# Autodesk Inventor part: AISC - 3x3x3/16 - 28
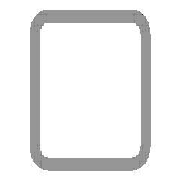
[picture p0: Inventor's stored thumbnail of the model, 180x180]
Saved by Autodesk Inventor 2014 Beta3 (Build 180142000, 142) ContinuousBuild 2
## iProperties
IsCustomPart: 1
_CCFamilyMember: 9
_CCFamilyDisplayName: ANSI AISC (Square) - Tube
_FrameMemberDoc: Frame Member File
_Version: 15.0.0
_GetPNFromCC: 1
Created: 2011-01
Part Number: AISC - 3x3x3/16 - 28
Material: Steel, Mild
Description: Tube
Document SubType Name: Modeling
Standard: ANSI
Designer: Beta-8540w
Standards Organization: ANSI
Language: en-US
Size Designation: 3x3x3/16
Categories: <MemberInstance><Categories><Category DisplayName="Structural Shapes" InternalName="089c4875-fa83-4c05-b084-43b9cc11f5ed" Mnemonic="GRDR"><CategoryParameter Dis
Stock Number: 3x3x3/16
Density: 7.86 g/cm^3
Appearance: Steel
G_L: 28.000 in
G_W: 3.000 in
G_H: 3.000 in
Author: Beta-8540w
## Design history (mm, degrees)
node "Start plane"
node "End plane"
sketch "Sketch"
  geometry: L1 (-38.1, -28.575)-(-38.1, 28.575); L2 (-28.575, 38.1)-(28.575, 38.1); L3 (38.1, 28.575)-(38.1, -28.575); L4 (28.575, -38.1)-(-28.575, -38.1); L5 (-28.575, 33.337)-(28.575, 33.338); L6 (33.338, 28.575)-(33.338, -28.575); L7 (28.575, -33.337)-(-28.575, -33.338); L8 (-33.338, -28.575)-(-33.338, 28.575); L9 (0, 56.102)-(0, -56.102) reference; L10 (-56.102, 0)-(56.102, 0) reference; A1 r 9.525 centre (-28.575, -28.575) between (-38.1, -28.575) and (-28.575, -38.1); A2 r 9.525 centre (-28.575, 28.575) between (-28.575, 38.1) and (-38.1, 28.575); A3 r 9.525 centre (28.575, 28.575) between (38.1, 28.575) and (28.575, 38.1); A4 r 9.525 centre (28.575, -28.575) between (28.575, -38.1) and (38.1, -28.575); A5 r 4.763 centre (-28.575, 28.575) between (-28.575, 33.337) and (-33.338, 28.575); A6 r 4.763 centre (28.575, 28.575) between (33.338, 28.575) and (28.575, 33.338); A7 r 4.763 centre (28.575, -28.575) between (28.575, -33.337) and (33.338, -28.575); A8 r 4.763 centre (-28.575, -28.575) between (-33.338, -28.575) and (-28.575, -33.338)
  constraints: 16 end point, 16 point on circle, 8 centre point, 8 tangent, 4 parallel, 3 equal radius, 2 perpendicular, 7 other
  dimensions: "d10" = 76.2 distance between parallel lines of L2 L4 (= G_H); "d11" = 76.2 distance between parallel lines of L1 L3 (= G_W); "d12" = 4.7625 distance between parallel lines of L3 L6 (= G_T); "d15" = 38.1 distance between parallel lines of L2 L10 (= 0.5 x d10); "d16" = 38.1 distance between parallel lines of L9 L3 (= 0.5 x d11); "d17" = 9.525 radius of A1 (= G_IR)
extrude "Body" new body sketch "Sketch" stored distance "d3" = 711.2 (= G_L); taper "d4" = 0 deg
node "Driven Length"
  sketch "Sketch3"
    geometry: L1 (0, 0)-(10, 0) reference
    constraints: 2 end point, 1 horizontal
  workplane "Work Plane3"
  sketch "Sketch4"
    geometry: L1 (-2, 0)-(12, 0) reference; L2 (-2, 711.2)-(12, 711.2) reference
    dimensions: "d19" = 711.2 distance between parallel lines of L1 L2 (derived)
body "Solid1"
other parameters: "G_W" = 76.2 [user parameter; used in 1 equation term], "G_H" = 76.2 [user parameter; used in 1 equation term], "G_T" = 4.7625 [user parameter; used in 1 equation term], "G_IR" = 9.525 [user parameter; used in 1 equation term], "G_L" = 711.2 (= d19) [user parameter; used in 1 equation term], "G_OFFSET_START" = 0 [user parameter; used in 1 equation term], "G_OFFSET_END" = 0 [user parameter; used in 1 equation term], "d13" = 0 (computed from G_OFFSET_START), "d14" = 711.2 (= G_OFFSET_END + B_L), "B_L" = 711.2 [user parameter; used in 1 equation term], "d18" = 90 deg
